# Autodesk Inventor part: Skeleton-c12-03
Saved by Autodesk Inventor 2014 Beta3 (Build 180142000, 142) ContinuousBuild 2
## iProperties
Created: 2011-01
Part Number: Skeleton-c12-03
Material: Generic
Document SubType Name: Modeling
Designer: Thom Tremblay
Density: 1 g/cm^3
Appearance: Generic
_SkeletonDoc: Frame Skeleton File
_Version: 15.0.0
Author: Thom Tremblay
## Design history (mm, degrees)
sketch "Reference Skeleton"
